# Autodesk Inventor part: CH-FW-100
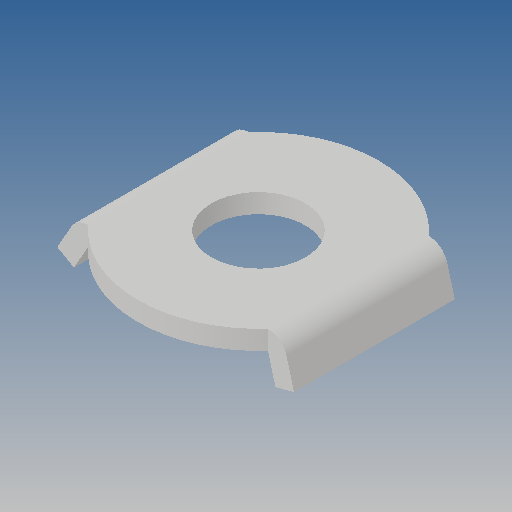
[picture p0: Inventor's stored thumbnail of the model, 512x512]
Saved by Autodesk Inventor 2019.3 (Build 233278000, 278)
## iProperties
Created: 2012-09
Part Number: CH-FW-100
Material: Ogólny
Document SubType Name: Modeling
Designer: CADENGINEERING4
Density: 1 g/cm^3
Appearance: Domyślna
Author: CADENGINEERING4
Revision Number: ÈÎºÎ
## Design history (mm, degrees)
feature "ÇÐ³ý-À­Éì1"
node "Bryła1"
